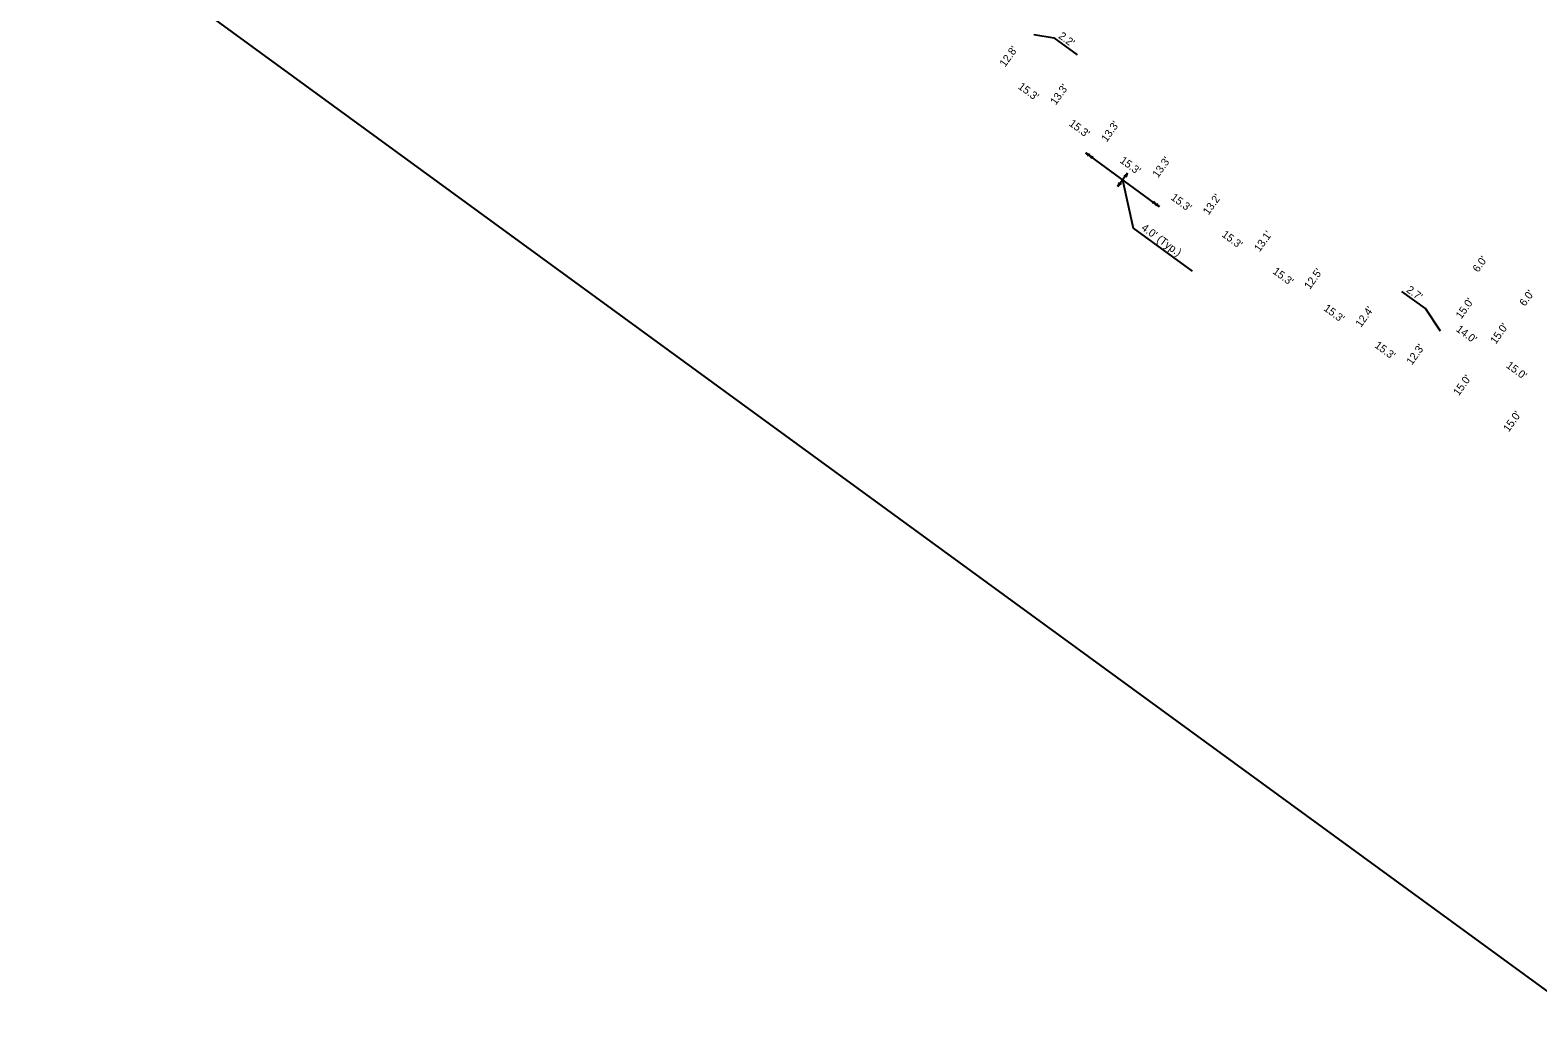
# Model space of a CAD drawing. Extents: x 15567221 to 15568484, y 8782768 to 8783889.
# Drawn here: x 15567746.9 to 15568114, y 8783008.6 to 8783249.6 of the extents above; entities that cross this region are included whole.
import ezdxf

# ---------------------------------------------------------------- set-up
doc = ezdxf.new("R2010")
doc.units = 0
for name, color, linetype in [('Drainage', 7, 'Continuous'), ('EXT_GU', 7, 'Continuous'), ('NamedBoundary', 7, 'Continuous')]:
    doc.layers.add(name, color=color, linetype=linetype)

msp = doc.modelspace()

# ---------------------------------------------------------------- linework, layer by layer
at = {"layer": 'Drainage'}
for p, q in [((15567991.24, 8783248.61), (15567996.19, 8783247.82)), ((15568001.91, 8783243.65), (15567996.19, 8783247.82)), ((15568021.85, 8783206.7), (15568003.93, 8783219.77)), ((15568014.07, 8783214.85), (15568011.71, 8783211.62)), ((15568012.89, 8783213.24), (15568015.45, 8783201.5)), ((15568015.45, 8783201.5), (15568029.8, 8783191.04)), ((15568086.6, 8783181.91), (15568080.88, 8783186.08)), ((15568090.27, 8783176.4), (15568086.6, 8783181.91))]:
    msp.add_line(p, q, dxfattribs=at)
at = {"layer": 'EXT_GU'}
for p, q in [((15568003.93, 8783219.77), (15568004.32, 8783219.48)), ((15568003.93, 8783219.77), (15568004.7, 8783219.2)), ((15568004.7, 8783219.2), (15568005.09, 8783218.92)), ((15568004.7, 8783219.2), (15568005.48, 8783218.64)), ((15568011.71, 8783211.62), (15568012.27, 8783212.4)), ((15568014.07, 8783214.85), (15568013.5, 8783214.08)), ((15568014.07, 8783214.85), (15568013.78, 8783214.46)), ((15568011.71, 8783211.62), (15568011.99, 8783212.01)), ((15568021.07, 8783207.27), (15568020.29, 8783207.84)), ((15568021.07, 8783207.27), (15568020.68, 8783207.55)), ((15568021.85, 8783206.7), (15568021.07, 8783207.27)), ((15568021.85, 8783206.7), (15568021.46, 8783206.99))]:
    msp.add_line(p, q, dxfattribs=at)
for centre, radius, start, end in [((15568002.67, 8783218.05), 2.12, 25.833, 53.9055), ((15568005.18, 8783221.49), 2.12, 233.9055, 261.978), ((15568005.37, 8783218.72), 0.821, 126.1722, 161.6389), ((15568003.45, 8783217.49), 2.12, 25.833, 53.9055), ((15568005.95, 8783220.92), 2.12, 233.9055, 261.978), ((15568006.14, 8783218.15), 0.821, 126.1722, 161.6389), ((15568009.99, 8783212.87), 2.12, 323.9055, 351.978), ((15568013.43, 8783210.37), 2.12, 115.833, 143.9055), ((15568012.76, 8783213.06), 0.821, 216.1722, 251.6389), ((15568012.35, 8783216.1), 2.12, 295.833, 323.9055), ((15568013.02, 8783213.41), 0.821, 36.1722, 71.6389), ((15568015.78, 8783213.6), 2.12, 143.9055, 171.978), ((15568019.63, 8783208.32), 0.821, 306.1722, 341.6389), ((15568019.82, 8783205.55), 2.12, 53.9055, 81.978), ((15568022.32, 8783208.99), 2.12, 205.833, 233.9055), ((15568020.41, 8783207.75), 0.821, 306.1722, 341.6389), ((15568020.6, 8783204.99), 2.12, 53.9055, 81.978), ((15568023.1, 8783208.42), 2.12, 205.833, 233.9055)]:
    msp.add_arc(centre, radius, start, end, dxfattribs=at)
at = {"layer": 'NamedBoundary'}
msp.add_lwpolyline([(15568248.32, 8782919.55), (15568483.96, 8783242.77), (15567982.56, 8783608.32), (15567746.92, 8783285.1)], close=True, dxfattribs=at)

# ---------------------------------------------------------------- texts
at = {"layer": 'Drainage'}
for s, height, rotation, p in [("2.2'", 1.89, 323.7364, (15567997.13, 8783247.87)), ("12.8'", 1.89, 54.3971, (15567984.29, 8783240.54)), ("15.3'", 1.89, 323.584, (15567987.27, 8783235.58)), ("13.3'", 1.89, 54.3971, (15567996.63, 8783231.3)), ("15.3'", 1.89, 323.584, (15567999.67, 8783226.59)), ("13.3'", 1.89, 54.3971, (15568009.02, 8783222.28)), ("15.3'", 1.89, 323.584, (15568012.07, 8783217.59)), ("13.3'", 1.89, 54.3971, (15568021.51, 8783213.59)), ("15.3'", 1.89, 323.584, (15568024.47, 8783208.6)), ("13.2'", 1.89, 54.3971, (15568033.81, 8783204.55)), ("4.0' (Typ.)", 1.8898, 323.7364, (15568017.27, 8783201.21)), ("15.3'", 1.89, 323.584, (15568036.87, 8783199.6)), ("13.1'", 1.89, 54.3971, (15568046.24, 8783195.57)), ("6.0'", 1.89, 53.9364, (15568099.45, 8783190.58)), ("15.3'", 1.89, 323.584, (15568049.27, 8783190.61)), ("12.5'", 1.89, 54.3971, (15568058.48, 8783186.43)), ("2.7'", 1.89, 323.7364, (15568081.82, 8783186.12)), ("6.0'", 1.89, 53.9364, (15568110.85, 8783182.32)), ("15.0'", 1.89, 54.3971, (15568095.34, 8783179.23)), ("15.3'", 1.89, 323.584, (15568061.68, 8783181.61)), ("12.4'", 1.89, 54.3971, (15568070.94, 8783177.19)), ("14.0'", 1.89, 323.3841, (15568093.91, 8783176.57)), ("15.0'", 1.89, 54.3971, (15568103.74, 8783173.11)), ("15.3'", 1.89, 323.584, (15568074.08, 8783172.62)), ("12.3'", 1.89, 54.3971, (15568083.34, 8783168.03)), ("15.0'", 1.89, 323.3841, (15568106.11, 8783167.73)), ("15.0'", 1.89, 54.3971, (15568094.74, 8783160.54)), ("15.0'", 1.89, 54.3971, (15568106.89, 8783151.73))]:
    msp.add_text(s, height=height, rotation=rotation, dxfattribs=at).set_placement(p)

doc.saveas('drawing.dxf')
